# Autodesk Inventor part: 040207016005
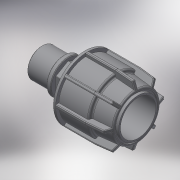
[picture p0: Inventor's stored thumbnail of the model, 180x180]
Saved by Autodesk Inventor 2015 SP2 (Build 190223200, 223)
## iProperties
Created: 2017-08
Part Number: 040207016005
Material: Generic
Description: PLASSON IRRIFIT ADAPTOR 16-1/2"M
Document SubType Name: Modeling
Designer: KIM
Density: 1 g/cm^3
Appearance: Default
Author: KIM
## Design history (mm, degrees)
derived "040207.ipt"
feature "Solid1::040207.ipt"
tag "TaggingFeature1"
body "Solid1"
other parameters: "d5" = 30.7, "d6" = 14.08, "d10" = 34, "d22" = 20.955, "d24" = 1.472, "d25" = 30.6, "d26" = 27.2, "d31" = 0.64, "d49" = 1.7, "d50" = 0, "d58" = 0.32, "d61" = 360 deg, "d77" = 16, "d78" = 5 deg, "d80" = 17.6, "d81" = 32, "d82" = 1.92, "d84" = 5 deg, "d85" = 70 deg, "d86" = 32.3, "d87" = 0.32, "d88" = 0, "d89" = 28.9, "d90" = 3.2, "d91" = 0, "d99" = 20.955, "d100" = 16, "d101" = 3.2, "d102" = 64, "d103" = 25.146, "d104" = 0.4191, "d108" = 0, "d109" = 0.20955, "d112" = 16, "d113" = 24.56, "d_" = 16, "E_" = 34, "H_" = 64, "l_nut" = 30.7, "l_" = 16, "R_" = 20.955
